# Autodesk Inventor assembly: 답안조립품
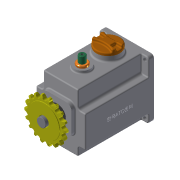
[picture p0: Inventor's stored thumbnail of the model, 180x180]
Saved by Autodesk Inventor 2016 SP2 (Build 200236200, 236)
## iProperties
Created: 2017-12
Part Number: 답안조립품
Document SubType Name: Assembly
Designer: Administrator
Author: Administrator
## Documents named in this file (17)
- D:\371207V1008\답안조립품.iam
- D:\371207V1008\본체.ipt
- D:\371207V1008\부시.ipt
- D:\371207V1008\슬라이더.ipt
- D:\371207V1008\스프로킷.ipt
- D:\371207V1008\오일 실 17 32 8.ipt
- D:\371207V1008\베어링 608.ipt
- D:\371207V1008\베어링 6003.ipt
- D:\371207V1008\메인축.ipt
- D:\371207V1008\서브축.ipt
- D:\371207V1008\키 5 x 5 x 18.ipt
- D:\371207V1008\상부 캡.ipt
- D:\371207V1008\멈춤나사 M3x8.ipt
- D:\371207V1008\커버.ipt
- D:\371207V1008\오일 실 8 22 7.ipt
- D:\371207V1008\볼트 M4 x 10.ipt
- D:\371207V1008\가변스프링.ipt
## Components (1 placed, 1 different names)
1. 가변스프링:1
